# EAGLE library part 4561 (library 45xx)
COMPLEMENTER
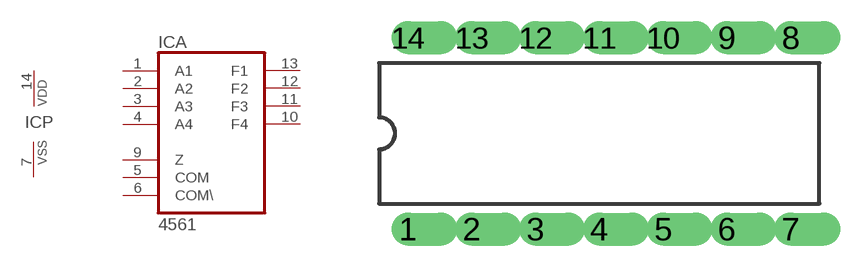
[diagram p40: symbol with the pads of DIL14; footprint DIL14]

Designator prefix IC; gates A=4561 P=PWRN

## 4561N  [DIL14]
1  A:A1  in
2  A:A2  in
3  A:A3  in
4  A:A4  in
5  A:COM  in
6  A:COM\  in
7  P:VSS  pwr
9  A:Z  in
10  A:F4  out
11  A:F3  out
12  A:F2  out
13  A:F1  out
14  P:VDD  pwr

## Footprint DIL14 (pad centres in mm)
Dual In Line
drill 0.813 offset: 1 -7.62,-3.81; 2 -5.08,-3.81; 3 -2.54,-3.81; 4 0,-3.81; 5 2.54,-3.81; 6 5.08,-3.81; 7 7.62,-3.81; 8 7.62,3.81; 9 5.08,3.81; 10 2.54,3.81; 11 0,3.81; 12 -2.54,3.81; 13 -5.08,3.81; 14 -7.62,3.81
